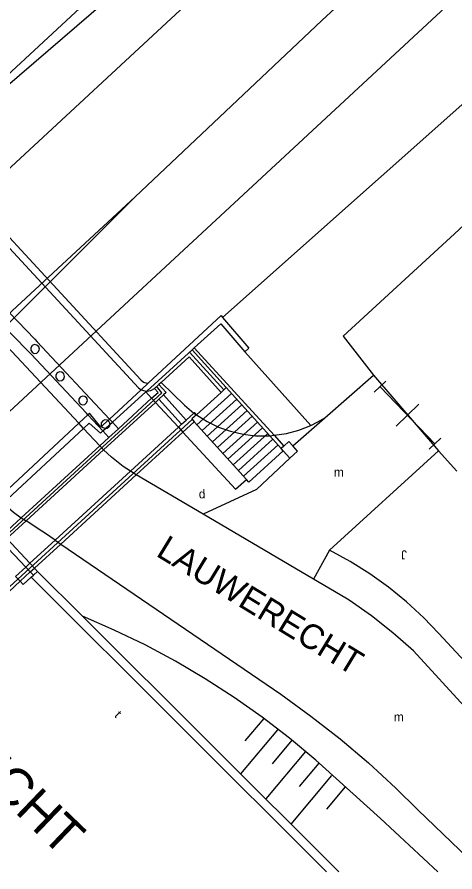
# Model space of a CAD drawing. Extents: x 134999 to 136502, y 457398 to 459002.
# Drawn here: x 136011.35 to 136036.09, y 457400 to 457448.25 of the extents above; entities that cross this region are included whole.
import ezdxf

# ---------------------------------------------------------------- set-up
doc = ezdxf.new("R2010")
doc.units = 0
for name, color, linetype in [('RI_DGTB_18', 7, 'Continuous'), ('RI_DGTB_28', 7, 'Continuous'), ('RI_DGTB_29', 7, 'Continuous'), ('RI_DGTB_31', 7, 'Continuous'), ('RI_DGTB_37', 7, 'Continuous'), ('RI_DGTB_38', 7, 'Continuous'), ('RI_DGTB_43', 7, 'Continuous'), ('RI_DGTB_48', 7, 'Continuous'), ('RI_DGTB_53', 7, 'Continuous'), ('RI_DGTB_54', 7, 'Continuous'), ('RI_DGTB_58', 7, 'Continuous')]:
    doc.layers.add(name, color=color, linetype=linetype)

msp = doc.modelspace()

# ---------------------------------------------------------------- linework, layer by layer
at = {"layer": 'RI_DGTB_18'}
for p, q in [((136021.339, 457425.901), (136021.481, 457425.804)), ((136025.29, 457408.662), (136024.225, 457407.391)), ((136026.056, 457408.02), (136023.974, 457405.535)), ((136026.872, 457407.436), (136025.758, 457406.106)), ((136027.643, 457406.799), (136025.396, 457404.117)), ((136028.4, 457406.145), (136027.291, 457404.822)), ((136029.122, 457405.45), (136026.818, 457402.7)), ((136029.889, 457404.808), (136028.824, 457403.537))]:
    msp.add_line(p, q, dxfattribs=at)
for points in [[(136027.941, 457425.2), (136028.343, 457425.401), (136028.73, 457425.629)], [(136035.126, 457400), (136031.892, 457403.006), (136028.61, 457405.959), (136028.224, 457406.3), (136026.734, 457407.547), (136025.194, 457408.731), (136023.607, 457409.852), (136021.974, 457410.906), (136020.3, 457411.892), (136018.587, 457412.808), (136016.837, 457413.653), (136015.054, 457414.425)]]:
    msp.add_lwpolyline(points, dxfattribs=at)
at = {"layer": 'RI_DGTB_28'}
for p, q in [((136002.038, 457431.476), (136044.622, 457470.94)), ((136012.492, 457429.925), (136016.576, 457425.56)), ((136022.876, 457427.065), (136021.481, 457425.804)), ((136023.464, 457427.008), (136021.509, 457425.239)), ((136023.171, 457427.332), (136022.876, 457427.065)), ((136025.632, 457424.621), (136023.171, 457427.332)), ((136019.362, 457426.678), (136020.642, 457425.262)), ((136019.628, 457426.921), (136020.908, 457425.506)), ((136023.757, 457426.685), (136021.802, 457424.916)), ((136024.05, 457426.361), (136022.095, 457424.592)), ((136024.342, 457426.038), (136022.387, 457424.269)), ((136016.201, 457424.888), (136015.351, 457425.798)), ((136016.576, 457425.56), (136016.743, 457425.381)), ((136024.635, 457425.714), (136022.68, 457423.945)), ((136016.743, 457425.381), (136017.073, 457425.016)), ((136021.356, 457425.408), (136024.313, 457422.141)), ((136024.928, 457425.391), (136022.973, 457423.622)), ((136025.221, 457425.067), (136023.266, 457423.298)), ((136016.201, 457424.888), (136016.533, 457424.527)), ((136025.513, 457424.744), (136023.558, 457422.975)), ((136026.272, 457423.904), (136025.632, 457424.621)), ((136025.806, 457424.42), (136023.851, 457422.651)), ((136026.099, 457424.097), (136024.144, 457422.328)), ((136026.391, 457423.774), (136026.272, 457423.904)), ((136011.262, 457416.679), (136011.522, 457416.408))]:
    msp.add_line(p, q, dxfattribs=at)
for points in [[(136018.029, 457438.107), (136028.57, 457448.058), (136116.844, 457529.556), (136123.03, 457535.178), (136141.207, 457551.252), (136159.733, 457567.276), (136171.103, 457576.881)], [(136000, 457415.892), (136092.119, 457501.222), (136126.526, 457532.85), (136145.405, 457549.48), (136163.787, 457565.389)], [(136002.017, 457436.847), (136037.283, 457469.498)], [(136002.017, 457436.847), (136038.487, 457468.202)], [(136015.27, 457425.884), (136012.14, 457429.231), (136006.37, 457435.07), (136001.58, 457440.27), (136002.19, 457440.83), (136007.03, 457435.59), (136012.346, 457430.072)], [(136000, 457421.425), (136018.029, 457438.107)], [(136000, 457420.135), (136018.029, 457438.107)], [(136012.124, 457429.446), (136012.197, 457429.326), (136012.322, 457429.265), (136012.461, 457429.28), (136012.57, 457429.368), (136012.615, 457429.501), (136012.615, 457429.511), (136012.576, 457429.645), (136012.47, 457429.738), (136012.332, 457429.759), (136012.204, 457429.702), (136012.126, 457429.586), (136012.124, 457429.446)], [(136013.538, 457427.905), (136013.611, 457427.785), (136013.736, 457427.724), (136013.875, 457427.739), (136013.984, 457427.827), (136014.029, 457427.96), (136014.029, 457427.97), (136013.99, 457428.104), (136013.884, 457428.197), (136013.746, 457428.218), (136013.618, 457428.161), (136013.54, 457428.045), (136013.538, 457427.905)], [(136014.833, 457426.546), (136014.906, 457426.426), (136015.031, 457426.365), (136015.17, 457426.38), (136015.279, 457426.468), (136015.324, 457426.601), (136015.324, 457426.611), (136015.285, 457426.745), (136015.179, 457426.838), (136015.041, 457426.859), (136014.913, 457426.802), (136014.835, 457426.686), (136014.833, 457426.546)], [(136021.481, 457425.804), (136021.216, 457425.563), (136021.356, 457425.408)], [(136016.479, 457425.47), (136016.453, 457425.492), (136016.315, 457425.513), (136016.187, 457425.456), (136016.109, 457425.34), (136016.107, 457425.2), (136016.136, 457425.152)], [(136016.35, 457425.024), (136016.305, 457425.019), (136016.18, 457425.08), (136016.136, 457425.152)], [(136016.595, 457425.246), (136016.553, 457425.122), (136016.444, 457425.034), (136016.35, 457425.024)], [(136016.479, 457425.47), (136016.559, 457425.399), (136016.598, 457425.265), (136016.598, 457425.255), (136016.595, 457425.246)], [(136026.391, 457423.774), (136024.436, 457422.005), (136024.313, 457422.141)], [(136012.143, 457416.63), (136011.696, 457416.221), (136011.522, 457416.408)]]:
    msp.add_lwpolyline(points, dxfattribs=at)
at = {"layer": 'RI_DGTB_48'}
for p, q in [((136021.358, 457429.575), (136025.866, 457424.643)), ((136025.866, 457424.643), (136026.419, 457424.037)), ((136036.189, 457422.619), (136035.155, 457423.774))]:
    msp.add_line(p, q, dxfattribs=at)
msp.add_lwpolyline([(136050.685, 457449.844), (136036.3, 457436.24), (136029.78, 457430.24), (136031.48, 457428.04)], dxfattribs=at)
at = {"layer": 'RI_DGTB_53'}
for p, q in [((136014.837, 457425.32), (136000.943, 457440.173)), ((136018.676, 457427.139), (136021.24, 457429.468)), ((136021.24, 457429.468), (136021.358, 457429.575)), ((136024.22, 457429.36), (136027.941, 457425.2)), ((136028.73, 457425.629), (136031.48, 457428.04)), ((136018.36, 457427.212), (136018.776, 457427.598)), ((136016.576, 457425.56), (136018.36, 457427.212)), ((136016.743, 457425.381), (136018.626, 457427.092)), ((136018.36, 457427.212), (136018.575, 457427.146)), ((136018.575, 457427.146), (136018.626, 457427.092)), ((136018.575, 457427.146), (136018.676, 457427.139)), ((136018.626, 457427.092), (136018.676, 457427.139)), ((136018.626, 457427.092), (136018.954, 457426.737)), ((136018.954, 457426.737), (136019.171, 457426.503)), ((136019.171, 457426.503), (136020.467, 457425.102)), ((136015.351, 457425.798), (136014.837, 457425.32)), ((136016.479, 457425.47), (136016.576, 457425.56)), ((136026.921, 457424.043), (136028.73, 457425.629)), ((136014.837, 457425.32), (136010.259, 457421.069)), ((136015.108, 457425.03), (136014.837, 457425.32)), ((136016.136, 457425.152), (136016.479, 457425.47)), ((136016.35, 457425.024), (136016.595, 457425.246)), ((136016.595, 457425.246), (136016.743, 457425.381)), ((136020.467, 457425.102), (136020.722, 457424.827)), ((136015.108, 457425.03), (136010.569, 457420.804)), ((136016.022, 457424.053), (136015.108, 457425.03)), ((136016.201, 457424.888), (136016.35, 457425.024)), ((136025.632, 457424.621), (136025.866, 457424.643)), ((136018.077, 457422.406), (136017.751, 457422.617)), ((136021.868, 457420.183), (136018.078, 457422.407)), ((136024.877, 457421.578), (136021.868, 457420.183)), ((136011.585, 457419.991), (136011.858, 457419.81)), ((136028.098, 457416.527), (136021.868, 457420.183)), ((136013.497, 457418.724), (136013.816, 457418.507)), ((136029.009, 457418.159), (136028.098, 457416.527)), ((136029.922, 457415.457), (136028.098, 457416.527))]:
    msp.add_line(p, q, dxfattribs=at)
for points in [[(136004.134, 457443.129), (136018.34, 457427.77), (136018.489, 457427.647), (136018.675, 457427.594), (136018.776, 457427.598)], [(136003.833, 457442.85), (136018.205, 457427.313), (136018.36, 457427.212)], [(136018.776, 457427.598), (136022.88, 457431.4), (136022.964, 457431.301)], [(136021.358, 457429.575), (136022.86, 457430.94), (136024.22, 457429.36)], [(136022.964, 457431.301), (136024.44, 457429.56), (136024.22, 457429.36)], [(136019.494, 457427.629), (136020.8, 457426.35), (136021.339, 457425.901)], [(136018.676, 457427.139), (136018.908, 457427.176), (136019.117, 457427.285)], [(136016.136, 457425.152), (136016.08, 457425.1), (136015.45, 457425.89), (136015.351, 457425.798)], [(136021.481, 457425.804), (136022.089, 457425.421), (136022.737, 457425.107), (136023.414, 457424.868), (136024.115, 457424.705), (136024.829, 457424.621), (136025.548, 457424.616), (136025.632, 457424.621)], [(136016.201, 457424.888), (136016.06, 457424.76), (136015.43, 457425.33), (136015.108, 457425.03)], [(136025.866, 457424.643), (136026.578, 457424.752), (136027.273, 457424.938), (136027.941, 457425.2)], [(136020.722, 457424.827), (136023.7, 457421.61), (136024.313, 457422.141)], [(136016.021, 457424.053), (136016.213, 457423.848), (136016.239, 457423.823)], [(136017.751, 457422.617), (136017.336, 457422.887), (136016.676, 457423.412), (136016.239, 457423.823)], [(136010.569, 457420.804), (136011.147, 457420.308), (136011.585, 457419.991)], [(136013.497, 457418.724), (136012.959, 457419.091), (136012.741, 457419.225), (136011.858, 457419.81)], [(136013.816, 457418.507), (136026.258, 457410.03), (136027.955, 457408.799), (136029.604, 457407.504), (136031.203, 457406.147), (136032.748, 457404.731), (136033.99, 457403.51), (136036.844, 457400.768), (136037.565, 457400)]]:
    msp.add_lwpolyline(points, dxfattribs=at)
at = {"layer": 'RI_DGTB_54'}
for p, q in [((136012.346, 457430.072), (136012.492, 457429.925)), ((136021.24, 457429.468), (136023.171, 457427.332)), ((136021.093, 457429.334), (136023.024, 457427.2)), ((136031.48, 457428.04), (136035.155, 457423.774)), ((136019.117, 457427.285), (136019.367, 457427.512)), ((136019.494, 457427.629), (136019.367, 457427.512)), ((136031.534, 457427.072), (136032.178, 457427.692)), ((136016.189, 457423.989), (136019.523, 457427.037)), ((136019.523, 457427.037), (136019.232, 457427.41)), ((136031.856, 457427.382), (136034.961, 457424.165)), ((136017.073, 457425.016), (136018.954, 457426.737)), ((136019.362, 457426.678), (136019.171, 457426.503)), ((136019.362, 457426.678), (136019.628, 457426.921)), ((136019.171, 457426.503), (136016.239, 457423.823)), ((136032.766, 457425.152), (136034.052, 457426.394)), ((136015.351, 457425.798), (136015.27, 457425.884)), ((136020.908, 457425.506), (136021.339, 457425.901)), ((136011.393, 457416.527), (136021.24, 457425.539)), ((136020.467, 457425.102), (136017.751, 457422.617)), ((136020.467, 457425.102), (136020.642, 457425.262)), ((136020.642, 457425.262), (136020.908, 457425.506)), ((136020.722, 457424.827), (136021.356, 457425.408)), ((136016.533, 457424.527), (136017.073, 457425.016)), ((136020.722, 457424.827), (136018.078, 457422.407)), ((136016.533, 457424.527), (136016.022, 457424.053)), ((136034.64, 457423.855), (136035.283, 457424.476)), ((136003.403, 457412.286), (136016.189, 457423.989)), ((136016.021, 457424.053), (136011.585, 457419.991)), ((136016.239, 457423.823), (136011.858, 457419.81)), ((136016.021, 457424.053), (136016.022, 457424.053)), ((136026.419, 457424.037), (136026.272, 457423.904)), ((136026.391, 457423.774), (136026.765, 457423.352)), ((136029.009, 457418.159), (136035.155, 457423.774)), ((136024.877, 457421.578), (136026.765, 457423.352)), ((136017.751, 457422.617), (136013.497, 457418.724)), ((136018.077, 457422.406), (136013.816, 457418.507)), ((136018.078, 457422.407), (136018.077, 457422.406)), ((136010.556, 457419.051), (136011.585, 457419.991)), ((136010.774, 457418.818), (136011.858, 457419.81)), ((136012.077, 457417.425), (136013.497, 457418.724)), ((136012.334, 457417.15), (136013.816, 457418.507)), ((136011.839, 457417.207), (136012.077, 457417.425)), ((136011.262, 457416.679), (136011.839, 457417.207)), ((136011.522, 457416.408), (136012.095, 457416.933)), ((136012.095, 457416.933), (136012.334, 457417.15)), ((136011.522, 457416.408), (136000, 457405.861)), ((136004.37, 457410.099), (136011.393, 457416.527))]:
    msp.add_line(p, q, dxfattribs=at)
for points in [[(136161.725, 457556.948), (136154.02, 457550.03), (136147.81, 457544.43), (136040.89, 457447.21), (136022.964, 457431.301)], [(136022.876, 457427.065), (136021.065, 457429.068), (136019.494, 457427.629)], [(136019.367, 457427.512), (136019.777, 457427.058), (136019.628, 457426.921)], [(136018.954, 457426.737), (136019.315, 457427.067), (136019.117, 457427.285)], [(136021.481, 457425.804), (136021.372, 457425.931), (136021.339, 457425.901)], [(136026.921, 457424.043), (136026.699, 457424.29), (136026.419, 457424.037)], [(136026.765, 457423.352), (136027.186, 457423.748), (136026.921, 457424.043)], [(136047.205, 457400), (136045.155, 457402.493), (136043.023, 457404.961), (136040.831, 457407.376), (136035.162, 457413.477), (136034.324, 457414.344), (136033.358, 457415.234), (136032.34, 457416.063), (136031.273, 457416.829), (136030.161, 457417.529), (136029.009, 457418.159)], [(136044.892, 457400), (136040.885, 457404.586), (136036.819, 457409.12), (136033.743, 457412.47), (136032.583, 457413.489), (136031.372, 457414.446), (136030.112, 457415.339), (136029.922, 457415.457)]]:
    msp.add_lwpolyline(points, dxfattribs=at)
at = {"layer": 'RI_DGTB_58'}
for p, q in [((136010.774, 457418.818), (136012.077, 457417.425)), ((136010.536, 457418.6), (136011.839, 457417.207)), ((136012.077, 457417.425), (136012.334, 457417.15)), ((136011.839, 457417.207), (136012.095, 457416.933)), ((136012.095, 457416.933), (136012.27, 457416.746)), ((136012.27, 457416.746), (136012.508, 457416.964)), ((136012.334, 457417.15), (136012.508, 457416.964)), ((136012.508, 457416.964), (136015.054, 457414.425)), ((136012.143, 457416.63), (136012.27, 457416.746)), ((136012.143, 457416.63), (136028.825, 457400)), ((136015.054, 457414.425), (136029.526, 457400))]:
    msp.add_line(p, q, dxfattribs=at)

# ---------------------------------------------------------------- texts
at = {"layer": 'RI_DGTB_29'}
msp.add_text('d', height=0.499, rotation=3.2426, dxfattribs=at).set_placement((136021.63, 457421.074))
at = {"layer": 'RI_DGTB_31'}
msp.add_text('J', height=0.5, rotation=180, dxfattribs=at).set_placement((136033.375, 457418.149))
at = {"layer": 'RI_DGTB_37'}
msp.add_text('LAUWERECHT', height=1.4, rotation=328.6405, dxfattribs=at).set_placement((136019.141, 457417.867))
at = {"layer": 'RI_DGTB_38'}
msp.add_text('VECHT', height=2.0989, rotation=316.1807, dxfattribs=at).set_placement((136007.013, 457407.377))
at = {"layer": 'RI_DGTB_43'}
for p in [(136029.253, 457422.315), (136032.64, 457408.5)]:
    msp.add_text('m', height=0.5, dxfattribs=at).set_placement(p)
msp.add_text('t', height=0.5, rotation=314.3845, dxfattribs=at).set_placement((136016.817, 457408.796))

doc.saveas('drawing.dxf')
